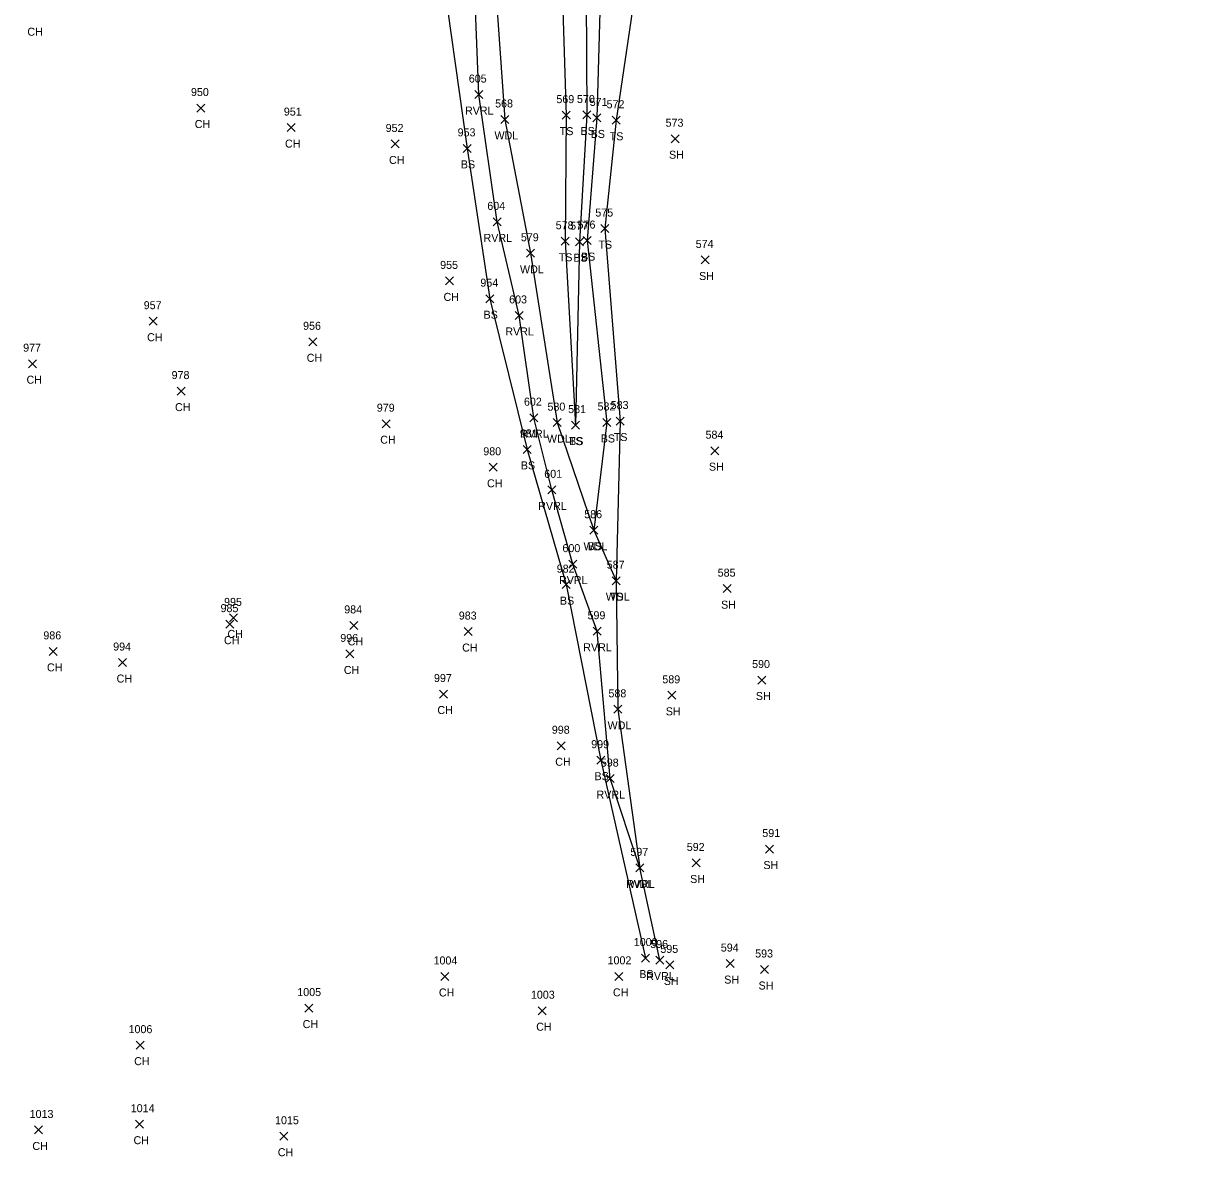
# Model space of a CAD drawing. Extents: x 1885914 to 1887218, y 756253 to 760620.
# Drawn here: x 1886746.1 to 1887041.6, y 759392.3 to 759675.3 of the extents above; entities that cross this region are included whole.
import ezdxf

# ---------------------------------------------------------------- set-up
doc = ezdxf.new("R2010")
doc.units = 0
for name, color, linetype in [('L_A', 7, 'Continuous'), ('L_I', 7, 'Continuous'), ('L_TIC', 7, 'Continuous'), ('LAWA', 7, 'Continuous'), ('LAWE', 7, 'Continuous'), ('LELB', 7, 'Continuous')]:
    doc.layers.add(name, color=color, linetype=linetype)

msp = doc.modelspace()

# ---------------------------------------------------------------- linework, layer by layer
at = {"layer": 'L_TIC'}
for points in [[(1886858.81, 759656.59), (1886860.81, 759658.59)], [(1886860.81, 759656.59), (1886858.81, 759658.59)], [(1886789.34, 759653.23), (1886791.34, 759655.23)], [(1886791.34, 759653.23), (1886789.34, 759655.23)], [(1886880.63, 759651.45), (1886882.63, 759653.45)], [(1886882.63, 759651.45), (1886880.63, 759653.45)], [(1886885.8, 759651.49), (1886887.8, 759653.49)], [(1886887.8, 759651.49), (1886885.8, 759653.49)], [(1886811.9, 759648.34), (1886813.9, 759650.34)], [(1886813.9, 759648.34), (1886811.9, 759650.34)], [(1886865.31, 759650.37), (1886867.31, 759652.37)], [(1886867.31, 759650.37), (1886865.31, 759652.37)], [(1886888.33, 759650.76), (1886890.33, 759652.76)], [(1886890.33, 759650.76), (1886888.33, 759652.76)], [(1886893.13, 759650.17), (1886895.13, 759652.17)], [(1886895.13, 759650.17), (1886893.13, 759652.17)], [(1886907.86, 759645.56), (1886909.86, 759647.56)], [(1886909.86, 759645.56), (1886907.86, 759647.56)], [(1886837.9, 759644.25), (1886839.9, 759646.25)], [(1886839.9, 759644.25), (1886837.9, 759646.25)], [(1886855.89, 759643.15), (1886857.89, 759645.15)], [(1886857.89, 759643.15), (1886855.89, 759645.15)], [(1886863.44, 759624.78), (1886865.44, 759626.78)], [(1886865.44, 759624.78), (1886863.44, 759626.78)], [(1886890.3, 759623.11), (1886892.3, 759625.11)], [(1886892.3, 759623.11), (1886890.3, 759625.11)], [(1886880.4, 759619.94), (1886882.4, 759621.94)], [(1886882.4, 759619.94), (1886880.4, 759621.94)], [(1886884, 759619.83), (1886886, 759621.83)], [(1886886, 759619.83), (1886884, 759621.83)], [(1886885.93, 759620.11), (1886887.93, 759622.11)], [(1886887.93, 759620.11), (1886885.93, 759622.11)], [(1886871.7, 759616.94), (1886873.7, 759618.94)], [(1886873.7, 759616.94), (1886871.7, 759618.94)], [(1886915.38, 759615.27), (1886917.38, 759617.27)], [(1886917.38, 759615.27), (1886915.38, 759617.27)], [(1886851.52, 759610.04), (1886853.52, 759612.04)], [(1886853.52, 759610.04), (1886851.52, 759612.04)], [(1886861.57, 759605.59), (1886863.57, 759607.59)], [(1886863.57, 759605.59), (1886861.57, 759607.59)], [(1886868.88, 759601.41), (1886870.88, 759603.41)], [(1886870.88, 759601.41), (1886868.88, 759603.41)], [(1886777.44, 759599.97), (1886779.44, 759601.97)], [(1886779.44, 759599.97), (1886777.44, 759601.97)], [(1886817.32, 759594.82), (1886819.32, 759596.82)], [(1886819.32, 759594.82), (1886817.32, 759596.82)], [(1886747.31, 759589.35), (1886749.31, 759591.35)], [(1886749.31, 759589.35), (1886747.31, 759591.35)], [(1886784.41, 759582.51), (1886786.41, 759584.51)], [(1886786.41, 759582.51), (1886784.41, 759584.51)], [(1886872.59, 759575.86), (1886874.59, 759577.86)], [(1886874.59, 759575.86), (1886872.59, 759577.86)], [(1886878.43, 759574.62), (1886880.43, 759576.62)], [(1886880.43, 759574.62), (1886878.43, 759576.62)], [(1886890.85, 759574.67), (1886892.85, 759576.67)], [(1886892.85, 759574.67), (1886890.85, 759576.67)], [(1886894.14, 759575.03), (1886896.14, 759577.03)], [(1886896.14, 759575.03), (1886894.14, 759577.03)], [(1886835.7, 759574.36), (1886837.7, 759576.36)], [(1886837.7, 759574.36), (1886835.7, 759576.36)], [(1886882.95, 759574.01), (1886884.95, 759576.01)], [(1886884.95, 759574.01), (1886882.95, 759576.01)], [(1886882.95, 759574.01), (1886884.95, 759576.01)], [(1886884.95, 759574.01), (1886882.95, 759576.01)], [(1886870.88, 759567.95), (1886872.88, 759569.95)], [(1886872.88, 759567.95), (1886870.88, 759569.95)], [(1886917.84, 759567.62), (1886919.84, 759569.62)], [(1886919.84, 759567.62), (1886917.84, 759569.62)], [(1886862.39, 759563.47), (1886864.39, 759565.47)], [(1886864.39, 759563.47), (1886862.39, 759565.47)], [(1886877.1, 759557.84), (1886879.1, 759559.84)], [(1886879.1, 759557.84), (1886877.1, 759559.84)], [(1886887.58, 759547.75), (1886889.58, 759549.75)], [(1886889.58, 759547.75), (1886887.58, 759549.75)], [(1886887.58, 759547.75), (1886889.58, 759549.75)], [(1886889.58, 759547.75), (1886887.58, 759549.75)], [(1886882.3, 759539.28), (1886884.3, 759541.28)], [(1886884.3, 759539.28), (1886882.3, 759541.28)], [(1886880.65, 759534.15), (1886882.65, 759536.15)], [(1886882.65, 759534.15), (1886880.65, 759536.15)], [(1886893.15, 759535.14), (1886895.15, 759537.14)], [(1886895.15, 759535.14), (1886893.15, 759537.14)], [(1886893.15, 759535.14), (1886895.15, 759537.14)], [(1886895.15, 759535.14), (1886893.15, 759537.14)], [(1886920.89, 759533.15), (1886922.89, 759535.15)], [(1886922.89, 759533.15), (1886920.89, 759535.15)], [(1886796.64, 759524.28), (1886798.64, 759526.28)], [(1886798.64, 759524.28), (1886796.64, 759526.28)], [(1886797.52, 759525.84), (1886799.52, 759527.84)], [(1886799.52, 759525.84), (1886797.52, 759527.84)], [(1886827.55, 759523.97), (1886829.55, 759525.97)], [(1886829.55, 759523.97), (1886827.55, 759525.97)], [(1886856.18, 759522.43), (1886858.18, 759524.43)], [(1886858.18, 759522.43), (1886856.18, 759524.43)], [(1886888.36, 759522.5), (1886890.36, 759524.5)], [(1886890.36, 759522.5), (1886888.36, 759524.5)], [(1886752.42, 759517.48), (1886754.42, 759519.48)], [(1886754.42, 759517.48), (1886752.42, 759519.48)], [(1886826.62, 759516.83), (1886828.62, 759518.83)], [(1886828.62, 759516.83), (1886826.62, 759518.83)], [(1886769.81, 759514.69), (1886771.81, 759516.69)], [(1886771.81, 759514.69), (1886769.81, 759516.69)], [(1886929.57, 759510.32), (1886931.57, 759512.32)], [(1886931.57, 759510.32), (1886929.57, 759512.32)], [(1886849.98, 759506.82), (1886851.98, 759508.82)], [(1886851.98, 759506.82), (1886849.98, 759508.82)], [(1886907.06, 759506.5), (1886909.06, 759508.5)], [(1886909.06, 759506.5), (1886907.06, 759508.5)], [(1886893.58, 759503), (1886895.58, 759505)], [(1886895.58, 759503), (1886893.58, 759505)], [(1886879.43, 759493.9), (1886881.43, 759495.9)], [(1886881.43, 759493.9), (1886879.43, 759495.9)], [(1886889.28, 759490.3), (1886891.28, 759492.3)], [(1886891.28, 759490.3), (1886889.28, 759492.3)], [(1886891.67, 759485.69), (1886893.67, 759487.69)], [(1886893.67, 759485.69), (1886891.67, 759487.69)], [(1886931.46, 759468.1), (1886933.46, 759470.1)], [(1886933.46, 759468.1), (1886931.46, 759470.1)], [(1886899.06, 759463.39), (1886901.06, 759465.39)], [(1886901.06, 759463.39), (1886899.06, 759465.39)], [(1886899.06, 759463.39), (1886901.06, 759465.39)], [(1886901.06, 759463.39), (1886899.06, 759465.39)], [(1886913.16, 759464.62), (1886915.16, 759466.62)], [(1886915.16, 759464.62), (1886913.16, 759466.62)], [(1886900.49, 759440.86), (1886902.49, 759442.86)], [(1886902.49, 759440.86), (1886900.49, 759442.86)], [(1886904.08, 759440.37), (1886906.08, 759442.37)], [(1886906.08, 759440.37), (1886904.08, 759442.37)], [(1886906.55, 759439.14), (1886908.55, 759441.14)], [(1886908.55, 759439.14), (1886906.55, 759441.14)], [(1886921.66, 759439.48), (1886923.66, 759441.48)], [(1886923.66, 759439.48), (1886921.66, 759441.48)], [(1886850.36, 759436.26), (1886852.36, 759438.26)], [(1886852.36, 759436.26), (1886850.36, 759438.26)], [(1886893.85, 759436.29), (1886895.85, 759438.29)], [(1886895.85, 759436.29), (1886893.85, 759438.29)], [(1886930.24, 759438), (1886932.24, 759440)], [(1886932.24, 759438), (1886930.24, 759440)], [(1886816.31, 759428.36), (1886818.31, 759430.36)], [(1886818.31, 759428.36), (1886816.31, 759430.36)], [(1886874.69, 759427.7), (1886876.69, 759429.7)], [(1886876.69, 759427.7), (1886874.69, 759429.7)], [(1886774.2, 759419.1), (1886776.2, 759421.1)], [(1886776.2, 759419.1), (1886774.2, 759421.1)], [(1886748.77, 759397.91), (1886750.77, 759399.91)], [(1886750.77, 759397.91), (1886748.77, 759399.91)], [(1886774.05, 759399.35), (1886776.05, 759401.35)], [(1886776.05, 759399.35), (1886774.05, 759401.35)], [(1886810.1, 759396.35), (1886812.1, 759398.35)], [(1886812.1, 759396.35), (1886810.1, 759398.35)]]:
    msp.add_lwpolyline(points, dxfattribs=at)
at = {"layer": 'LAWA'}
msp.add_lwpolyline([(1887039.67, 759867.12), (1886997.46, 759866.5), (1886967.79, 759862.83), (1886953.9, 759859.39), (1886912.83, 759842.69), (1886895.91, 759826.12), (1886876.51, 759800.34), (1886870.46, 759780.62), (1886866.61, 759757.15), (1886861.71, 759722.13), (1886864, 759684.51), (1886866.31, 759651.37), (1886872.7, 759617.94), (1886879.43, 759575.62), (1886888.58, 759548.75), (1886894.15, 759536.14), (1886894.58, 759504), (1886900.06, 759464.39)], dxfattribs=at)
at = {"layer": 'LAWE'}
msp.add_lwpolyline([(1886905.08, 759441.37), (1886900.06, 759464.39), (1886892.67, 759486.69), (1886889.36, 759523.5), (1886883.3, 759540.28), (1886878.1, 759558.84), (1886873.59, 759576.86), (1886869.88, 759602.41), (1886864.44, 759625.78), (1886859.81, 759657.59), (1886858.79, 759683.07)], dxfattribs=at)
at = {"layer": 'LELB'}
for points in [[(1887041.64, 759890.67), (1887013.9, 759902.67), (1886998.82, 759910.39), (1886969.52, 759917.55), (1886930.15, 759916.74), (1886912.72, 759907.09), (1886894.42, 759890.67), (1886880.9, 759884.96), (1886854.09, 759848.47), (1886840.08, 759816.36), (1886838.53, 759797.02), (1886821.58, 759765.7), (1886826.94, 759738), (1886825.11, 759733.57), (1886845.96, 759724.49), (1886848.98, 759700.26), (1886856.89, 759644.15), (1886862.57, 759606.59), (1886871.88, 759568.95), (1886881.65, 759535.15), (1886890.28, 759491.3), (1886901.49, 759441.86)], [(1886900.21, 759785.53), (1886898.81, 759752.74), (1886899.95, 759718.8), (1886899.02, 759684.03), (1886894.13, 759651.17), (1886891.3, 759624.11), (1886895.14, 759576.03), (1886894.15, 759536.14)], [(1886885.89, 759781.45), (1886883.66, 759753.02), (1886883.87, 759716.81), (1886886.69, 759681.89), (1886886.8, 759652.49), (1886885, 759620.83), (1886883.95, 759575.01)], [(1886892.35, 759781.35), (1886888.03, 759753.48), (1886891.8, 759719.71), (1886890.27, 759684.28), (1886889.33, 759651.76), (1886886.93, 759621.11), (1886891.85, 759575.67), (1886888.58, 759548.75)], [(1886882.42, 759779.72), (1886878.98, 759752.77), (1886875.78, 759717.53), (1886880.76, 759681.44), (1886881.63, 759652.45), (1886881.4, 759620.94), (1886883.95, 759575.01)]]:
    msp.add_lwpolyline(points, dxfattribs=at)

# ---------------------------------------------------------------- texts
at = {"layer": 'L_A'}
for s, p in [('CH', (1886747, 759672.29)), ('RVRL', (1886856.37, 759652.59)), ('CH', (1886788.83, 759649.23)), ('WDL', (1886863.73, 759646.37)), ('TS', (1886880.04, 759647.45)), ('BS', (1886885.24, 759647.49)), ('BS', (1886887.77, 759646.76)), ('TS', (1886892.54, 759646.17)), ('CH', (1886811.38, 759644.34)), ('CH', (1886837.39, 759640.25)), ('SH', (1886907.35, 759641.56)), ('BS', (1886855.33, 759639.15)), ('RVRL', (1886861, 759620.78)), ('TS', (1886889.71, 759619.11)), ('TS', (1886879.81, 759615.94)), ('BS', (1886883.44, 759615.83)), ('BS', (1886885.37, 759616.11)), ('WDL', (1886870.11, 759612.94)), ('SH', (1886914.87, 759611.27)), ('CH', (1886851.01, 759606.04)), ('BS', (1886861.01, 759601.59)), ('CH', (1886776.93, 759595.97)), ('RVRL', (1886866.45, 759597.41)), ('CH', (1886816.81, 759590.82)), ('CH', (1886746.8, 759585.35)), ('CH', (1886783.9, 759578.51)), ('RVRL', (1886870.15, 759571.86)), ('CH', (1886835.19, 759570.36)), ('WDL', (1886876.84, 759570.62)), ('TS', (1886882.36, 759570.01)), ('BS', (1886882.39, 759570.01)), ('BS', (1886890.29, 759570.67)), ('TS', (1886893.55, 759571.03)), ('BS', (1886870.32, 759563.95)), ('SH', (1886917.33, 759563.62)), ('CH', (1886861.88, 759559.47)), ('RVRL', (1886874.66, 759553.84)), ('WDL', (1886885.99, 759543.75)), ('BS', (1886887.02, 759543.75)), ('RVRL', (1886879.86, 759535.28)), ('BS', (1886880.09, 759530.15)), ('WDL', (1886891.57, 759531.14)), ('TS', (1886892.56, 759531.14)), ('SH', (1886920.37, 759529.15)), ('CH', (1886797.01, 759521.84)), ('CH', (1886796.13, 759520.28)), ('CH', (1886827.04, 759519.97)), ('CH', (1886855.67, 759518.43)), ('RVRL', (1886885.92, 759518.5)), ('CH', (1886751.9, 759513.48)), ('CH', (1886826.1, 759512.83)), ('CH', (1886769.3, 759510.69)), ('SH', (1886929.06, 759506.32)), ('CH', (1886849.47, 759502.82)), ('SH', (1886906.55, 759502.5)), ('WDL', (1886892, 759499)), ('CH', (1886878.92, 759489.9)), ('BS', (1886888.73, 759486.3)), ('RVRL', (1886889.23, 759481.69)), ('SH', (1886930.95, 759464.1)), ('RVRL', (1886896.63, 759459.39)), ('WDL', (1886897.48, 759459.39)), ('SH', (1886912.64, 759460.62)), ('BS', (1886899.93, 759436.86)), ('RVRL', (1886901.65, 759436.37)), ('SH', (1886906.04, 759435.14)), ('SH', (1886921.15, 759435.48)), ('SH', (1886929.73, 759434)), ('CH', (1886849.85, 759432.26)), ('CH', (1886893.34, 759432.29)), ('CH', (1886815.8, 759424.36)), ('CH', (1886874.17, 759423.7)), ('CH', (1886773.69, 759415.1)), ('CH', (1886773.54, 759395.35)), ('CH', (1886748.26, 759393.91)), ('CH', (1886809.59, 759392.35))]:
    msp.add_text(s, height=2, dxfattribs=at).set_placement(p)
at = {"layer": 'L_I'}
for s, p in [('605', (1886857.32, 759660.59)), ('950', (1886787.89, 759657.23)), ('568', (1886863.9, 759654.37)), ('569', (1886879.21, 759655.45)), ('570', (1886884.35, 759655.49)), ('571', (1886887.54, 759654.76)), ('951', (1886811.1, 759652.34)), ('572', (1886891.76, 759654.17)), ('573', (1886906.5, 759649.56)), ('952', (1886836.54, 759648.25)), ('953', (1886854.53, 759647.15)), ('604', (1886861.95, 759628.78)), ('575', (1886888.94, 759627.11)), ('578', (1886879.04, 759623.94)), ('577', (1886882.64, 759623.83)), ('576', (1886884.51, 759624.11)), ('579', (1886870.33, 759620.94)), ('574', (1886914.02, 759619.27)), ('955', (1886850.16, 759614.04)), ('954', (1886860.21, 759609.59)), ('957', (1886776.08, 759603.97)), ('603', (1886867.4, 759605.41)), ('956', (1886815.91, 759598.82)), ('977', (1886745.95, 759593.35)), ('978', (1886783.05, 759586.51)), ('979', (1886834.33, 759578.36)), ('602', (1886871.1, 759579.86)), ('580', (1886876.98, 759578.62)), ('581', (1886882.15, 759578.01)), ('581', (1886882.15, 759578.01)), ('582', (1886889.49, 759578.67)), ('583', (1886892.78, 759579.03)), ('981', (1886870.09, 759571.95)), ('584', (1886916.48, 759571.62)), ('980', (1886860.94, 759567.47)), ('601', (1886876.18, 759561.84)), ('586', (1886886.16, 759551.75)), ('586', (1886886.16, 759551.75)), ('600', (1886880.72, 759543.28)), ('587', (1886891.79, 759539.14)), ('587', (1886891.79, 759539.14)), ('982', (1886879.29, 759538.15)), ('585', (1886919.52, 759537.15)), ('985', (1886795.28, 759528.28)), ('995', (1886796.16, 759529.84)), ('984', (1886826.19, 759527.97)), ('983', (1886854.82, 759526.43)), ('599', (1886886.99, 759526.5)), ('986', (1886751, 759521.48)), ('994', (1886768.45, 759518.69)), ('996', (1886825.2, 759520.83)), ('590', (1886928.12, 759514.32)), ('997', (1886848.62, 759510.82)), ('589', (1886905.69, 759510.5)), ('588', (1886892.22, 759507)), ('998', (1886878.07, 759497.9)), ('999', (1886887.91, 759494.3)), ('598', (1886890.31, 759489.69)), ('591', (1886930.67, 759472.1)), ('592', (1886911.79, 759468.62)), ('597', (1886897.7, 759467.39)), ('597', (1886897.7, 759467.39)), ('1000', (1886898.55, 759444.86)), ('596', (1886902.66, 759444.37)), ('595', (1886905.19, 759443.14)), ('594', (1886920.3, 759443.48)), ('593', (1886928.88, 759442)), ('1004', (1886848.51, 759440.26)), ('1002', (1886892, 759440.29)), ('1005', (1886814.46, 759432.36)), ('1003', (1886872.84, 759431.7)), ('1006', (1886772.29, 759423.1)), ('1014', (1886772.84, 759403.35)), ('1013', (1886747.57, 759401.91)), ('1015', (1886808.9, 759400.35))]:
    msp.add_text(s, height=2, dxfattribs=at).set_placement(p)

doc.saveas('drawing.dxf')
